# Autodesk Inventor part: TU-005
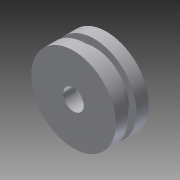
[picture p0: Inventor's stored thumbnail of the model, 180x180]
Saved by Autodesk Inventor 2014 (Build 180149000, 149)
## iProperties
Created: 2008-06
Part Number: TU-005
Document SubType Name: Modeling
Designer: PN
Density: 2.71 g/cm^3
Material: Aluminum-6061
Description: Piston
Mass: 37.1113 g
Surface Area: 62.8633 cm^2
Volume: 13.6942 cm^3
Appearance: Aluminum - Flat
Author: PN
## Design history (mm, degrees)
sketch "Sketch1"
  geometry: L1 (5, 0)-(5, 6); L2 (5, 6)-(13, 6); L3 (13, 6)-(13, 16); L4 (17, 10)-(17, 6); L5 (13, 16)-(20.5, 16); L6 (20.5, 16)-(20.5, 10); L7 (20.5, 10)-(17, 10); L8 (17, 6)-(20.5, 6); L9 (20.5, 6)-(20.5, 0); L10 (20.5, 0)-(5, 0); L11 (0, 0)-(0, 16)
  constraints: 22 end point, 2 collinear, 2 horizontal alignment, 1 horizontal, 1 perpendicular
  dimensions: "d0" = 10 diameter of L1 L11; "d1" = 26 diameter of L3 L11; "d2" = 34 diameter of L4 L11; "d3" = 41 diameter of L9 L11; "d4" = 6 distance between parallel lines of L8 L10; "d5" = 10 distance between parallel lines of L7 L10; "d6" = 16 distance between parallel lines of L5 L10
revolve "Revolution1" sketch "Sketch1" stored, may be unused: angle "d7" = 90 deg
body "Solid1"
